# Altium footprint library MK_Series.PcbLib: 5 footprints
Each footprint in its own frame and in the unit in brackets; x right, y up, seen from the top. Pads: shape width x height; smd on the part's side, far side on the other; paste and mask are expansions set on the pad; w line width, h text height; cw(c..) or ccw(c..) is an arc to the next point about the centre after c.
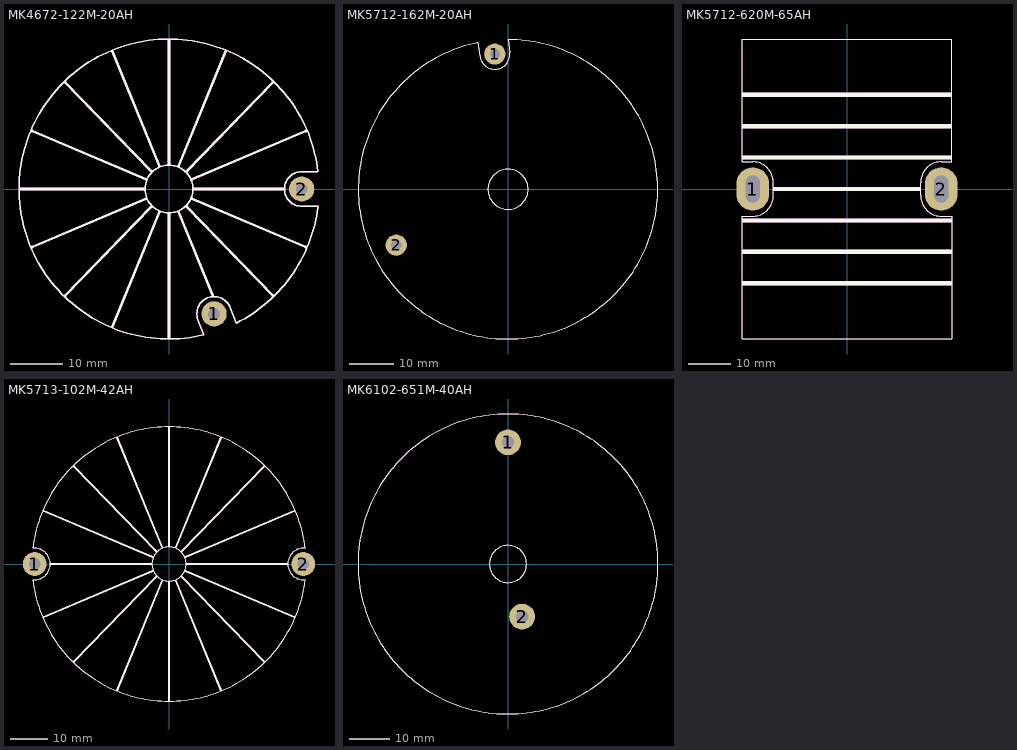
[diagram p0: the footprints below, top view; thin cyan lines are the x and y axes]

## MK4672-122M-20AH [mil]
pads (2):
  round 190 hole 90: 1(340,-940) 2(1000,0)
Top Overlay:
  circle w10: c0,0 r180
  lines w10: 1122.44,130 1000,130 ccw(c1000,0) 1000,-130 1122.5,-130 cw(c0,0) 505.35,-1010.7 462.16,-895.54 ccw(c340,-940) 217.84,-984.46 261.63,-1099.3 cw(c0,0) -1121.22,-140.55 cw(c0,0) 1122.44,130.47
  lines w19.68: -1125,0 -188,0 ; -1030.84,-436.8 -173.51,-73.52 ; -1030.84,436.8 -173.51,73.52 ; -783.73,-804.24 -132.54,-132.54 ; -783.73,804.24 -132.54,132.54 ; -427.02,-1039.12 -71.42,-171.47 ; -427.02,1039.12 -71.42,171.47 ; 0,-1125 0,-185 ; 0,185 0,1125 ; 71.42,-171.47 329.88,-802.1 ; 71.42,171.47 427.02,1039.12 ; 132.54,-132.54 783.73,-804.24 ; 132.54,132.54 783.73,804.24 ; 173.51,-73.52 1030.84,-436.8 ; 173.51,73.52 1030.84,436.8 ; 188,0 865,0
Mechanical 29:
  circle w10: c0,0 r180
  lines w10: 1122.44,130 1000,130 ccw(c1000,0) 1000,-130 1122.5,-130 cw(c0,0) 505.35,-1010.7 462.16,-895.54 ccw(c340,-940) 217.84,-984.46 261.63,-1099.3 cw(c0,0) -1121.22,-140.55 cw(c0,0) 1122.44,130.47
  lines w19.68: -1125,0 -188,0 ; -1030.84,-436.8 -173.51,-73.52 ; -1030.84,436.8 -173.51,73.52 ; -783.73,-804.24 -132.54,-132.54 ; -783.73,804.24 -132.54,132.54 ; -427.02,-1039.12 -71.42,-171.47 ; -427.02,1039.12 -71.42,171.47 ; 0,-1125 0,-185 ; 0,185 0,1125 ; 71.42,-171.47 329.88,-802.1 ; 71.42,171.47 427.02,1039.12 ; 132.54,-132.54 783.73,-804.24 ; 132.54,132.54 783.73,804.24 ; 173.51,-73.52 1030.84,-436.8 ; 173.51,73.52 1030.84,436.8 ; 188,0 865,0
  text "'.Designator'" at -1750,-64.83 h400

## MK5712-162M-20AH [mil]
pads (2):
  round 190 hole 90: 1(-118,1210) 2(-1000,-500)
Top Overlay:
  circle w10: c0,0 r180
  lines w10: -269.51,1312.62 ccw(c0,0) -1329.59,-166.67 ccw(c0,0) 1333.3,133.83 ccw(c0,0) 0,1340 16.26,1224.11 cw(c-118,1210) -252.26,1195.89 -268.66,1312.74
Mechanical 29:
  circle w10: c0,0 r180
  lines w10: -269.51,1312.62 ccw(c0,0) -1329.59,-166.67 ccw(c0,0) 1333.3,133.83 ccw(c0,0) 0,1340 16.26,1224.11 cw(c-118,1210) -252.26,1195.89 -268.66,1312.74
  text "'.Designator'" at -1750,-64.83 h400

## MK5712-620M-65AH [mil]
pads (2):
  oval 300x400 hole 130 slot 250 at 90 deg: 1(-870,0) 2(870,0)
Top Overlay:
  lines w10: -965,-1385 965,-1385 965,-250 870,-250 cw(c870,-60) 680,-60 680,60 cw(c870,60) 870,250 965,250 965,1385 -965,1385 -965,250 -870,250 cw(c-870,60) -680,60 -680,-60 cw(c-870,-60) -870,-250 -965,-250 -965,-1385
  lines w19.68: -960,-880 960,-880 ; -960,-860 960,-860 ; -960,-590 960,-590 ; -960,-570 960,-570 ; -960,-300 960,-300 ; -960,-280 960,-280 ; -960,280 960,280 ; -960,300 960,300 ; -960,570 960,570 ; -960,590 960,590 ; -960,860 960,860 ; -960,880 960,880 ; -675,-10 675,-10 ; -675,10 675,10
Mechanical 29:
  lines w10: -965,-1385 965,-1385 965,-250 870,-250 cw(c870,-60) 680,-60 680,60 cw(c870,60) 870,250 965,250 965,1385 -965,1385 -965,250 -870,250 cw(c-870,60) -680,60 -680,-60 cw(c-870,-60) -870,-250 -965,-250 -965,-1385
  lines w19.68: -960,-880 960,-880 ; -960,-860 960,-860 ; -960,-590 960,-590 ; -960,-570 960,-570 ; -960,-300 960,-300 ; -960,-280 960,-280 ; -960,280 960,280 ; -960,300 960,300 ; -960,570 960,570 ; -960,590 960,590 ; -960,860 960,860 ; -960,880 960,880 ; -675,-10 675,-10 ; -675,10 675,10
  text "'.Designator'" at -1750,-64.83 h400

## MK5713-102M-42AH [mil]
pads (2):
  round 250 hole 122: 1(-1415,0) 2(1415,0)
Top Overlay:
  circle w10: c0,0 r180
  lines w10: 1435.51,-163.72 cw(c1415,0) 1435.7,163.7 ccw(c0,0) -1435.7,163.7 cw(c-1415,0) -1435.7,-163.7 ccw(c0,0) 1435.61,-164.5
  lines w19.68: -1324.45,-561.21 -173.51,-73.52 ; -1324.45,561.21 -173.51,73.52 ; -1245,0 -188,0 ; -1002.61,-1030.02 -132.54,-132.54 ; -1002.61,1030.02 -132.54,132.54 ; -546.77,-1331.32 -71.42,-171.47 ; -546.77,1331.32 -71.42,171.47 ; 0,-1440 0,-185 ; 0,185 0,1440 ; 71.42,-171.47 546.77,-1331.32 ; 71.42,171.47 546.77,1331.32 ; 132.54,-132.54 1002.61,-1030.02 ; 132.54,132.54 1002.61,1030.02 ; 173.51,-73.52 1324.45,-561.21 ; 173.51,73.52 1324.45,561.21 ; 188,0 1245,0
Mechanical 29:
  circle w10: c0,0 r180
  lines w10: 1435.51,-163.72 cw(c1415,0) 1435.7,163.7 ccw(c0,0) -1435.7,163.7 cw(c-1415,0) -1435.7,-163.7 ccw(c0,0) 1435.61,-164.5
  lines w19.68: -1324.45,-561.21 -173.51,-73.52 ; -1324.45,561.21 -173.51,73.52 ; -1245,0 -188,0 ; -1002.61,-1030.02 -132.54,-132.54 ; -1002.61,1030.02 -132.54,132.54 ; -546.77,-1331.32 -71.42,-171.47 ; -546.77,1331.32 -71.42,171.47 ; 0,-1440 0,-185 ; 0,185 0,1440 ; 71.42,-171.47 546.77,-1331.32 ; 71.42,171.47 546.77,1331.32 ; 132.54,-132.54 1002.61,-1030.02 ; 132.54,132.54 1002.61,1030.02 ; 173.51,-73.52 1324.45,-561.21 ; 173.51,73.52 1324.45,561.21 ; 188,0 1245,0
  text "'.Designator'" at -1750,-64.83 h400

## MK6102-651M-40AH [mil]
pads (2):
  round 250 hole 120: 1(0,1180) 2(136.8,-510)
Top Overlay:
  circle w10: c0,0 r180
  lines w10: 1447.72,145.32 ccw(c0,0) -1443.7,-180.98 ccw(c0,0) 1447.73,145.32
Mechanical 29:
  circle w10: c0,0 r180
  lines w10: 1447.72,145.32 ccw(c0,0) -1443.7,-180.98 ccw(c0,0) 1447.73,145.32
  text "'.Designator'" at -1750,-64.83 h400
